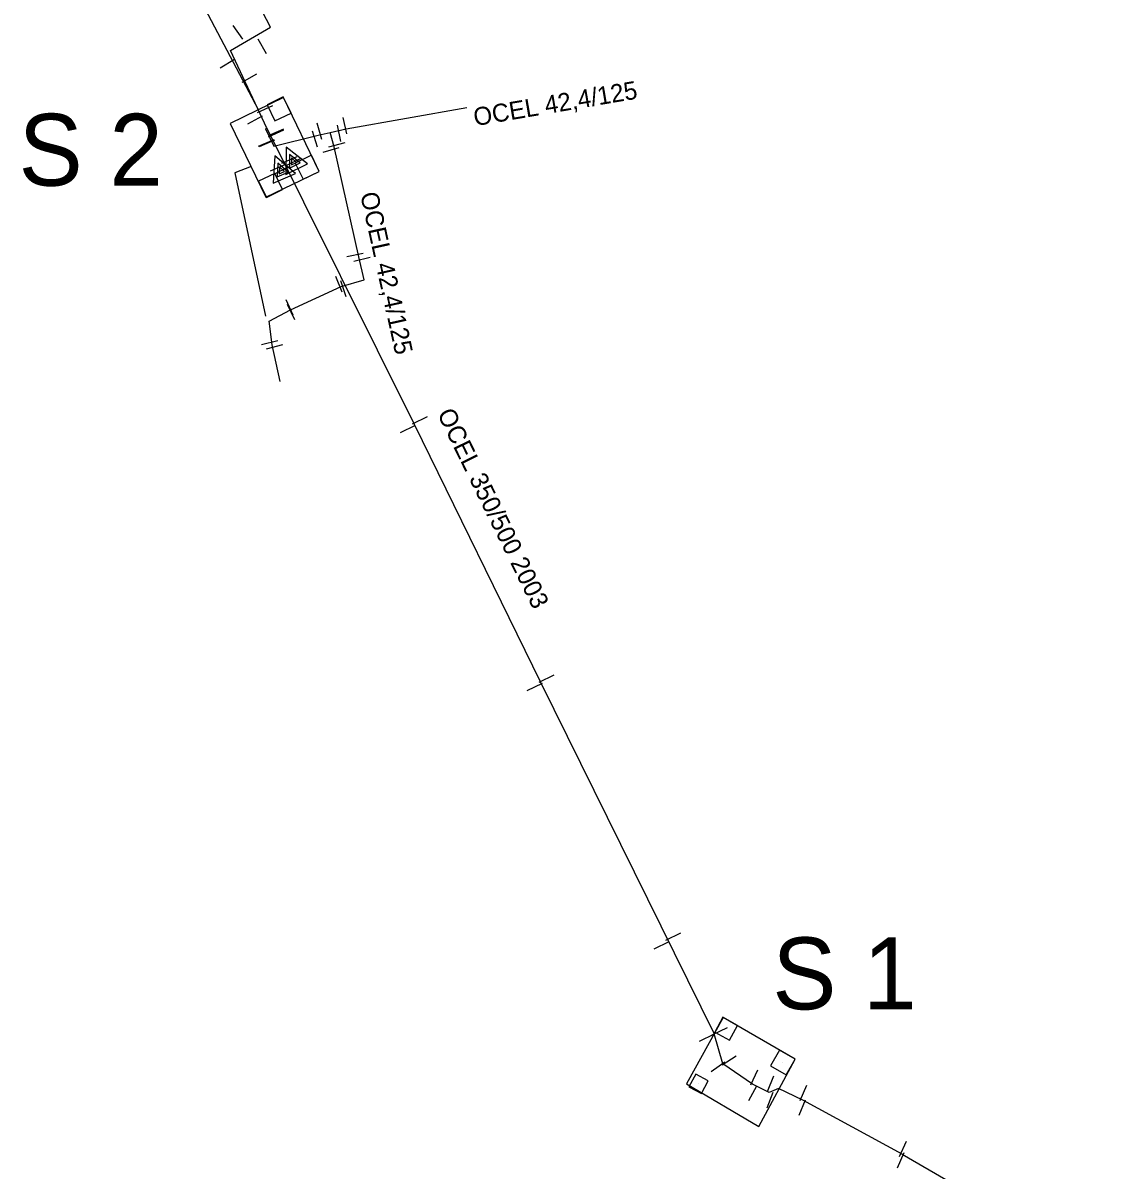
# Model space of a CAD drawing. Extents: x -642943 to -623314, y -1138561 to -1113539.
# Drawn here: x -642256.12 to -642210.58, y -1114828.93 to -1114781.07 of the extents above; entities that cross this region are included whole.
import ezdxf

# ---------------------------------------------------------------- set-up
doc = ezdxf.new("R2010")
doc.units = 0
for name, color, linetype in [('horkovod armatury', 7, 'Continuous'), ('horkovod dimenze', 7, 'Continuous'), ('horkovod předisol', 7, 'Continuous'), ('horkovod sváry', 7, 'Continuous'), ('horkovod trasa', 7, 'Continuous'), ('horkovod zrušený', 7, 'Continuous'), ('horkovod číslo šachty', 7, 'Continuous'), ('horkovod šachty', 7, 'Continuous')]:
    doc.layers.add(name, color=color, linetype=linetype)

# ---------------------------------------------------------------- blocks, each defined once
blk = doc.blocks.new('SPH')
at = {"layer": 'horkovod sváry'}
blk.add_line((0, -0.035), (0, 0.035), dxfattribs=at)
blk = doc.blocks.new('SPH_1')
at = {"layer": 'horkovod sváry'}
blk.add_line((0.0001, -0.035), (-0.0001, 0.035), dxfattribs=at)
blk = doc.blocks.new('SPH_2')
at = {"layer": 'horkovod sváry'}
blk.add_line((-0.0001, -0.0349), (0.0001, 0.0349), dxfattribs=at)
blk = doc.blocks.new('POINT_DISPLAY')
blk.add_line((0, 0), (0, 0))
blk = doc.blocks.new('PREDU_1')
at = {"layer": 'horkovod armatury'}
for p, q in [((-0.0007, 0.0677), (-0.0502, -0.0344)), ((0.0509, -0.0333), (-0.0007, 0.0677)), ((-0.0003, 0.0342), (-0.0249, -0.0171)), ((-0.0002, 0.0177), (-0.0119, -0.0084)), ((0.0251, -0.0166), (-0.0003, 0.0342)), ((0.0121, -0.0082), (-0.0002, 0.0177)), ((-0.0502, -0.0344), (0.0509, -0.0333)), ((-0.0249, -0.0171), (0.0251, -0.0166)), ((-0.0119, -0.0084), (0.0121, -0.0082))]:
    blk.add_line(p, q, dxfattribs=at)

msp = doc.modelspace()

# ---------------------------------------------------------------- linework, layer by layer
at = {"layer": 'horkovod předisol'}
for points in [[(-642245.948, -1114785.437), (-642246.214, -1114784.867), (-642247.454, -1114782.219), (-642245.787, -1114781.256), (-642247.074, -1114778.76), (-642248.776, -1114779.538), (-642252.188, -1114776.215)], [(-642243.291, -1114785.642), (-642242.626, -1114785.494), (-642237.585, -1114784.597)], [(-642245.948, -1114785.437), (-642245.998, -1114785.499), (-642245.641, -1114786.213), (-642243.799, -1114785.756), (-642243.291, -1114785.642)], [(-642245.948, -1114785.437), (-642239.784, -1114797.816), (-642234.509, -1114808.578), (-642227.271, -1114823.247)], [(-642245.387, -1114796.038), (-642245.71, -1114794.498), (-642245.834, -1114793.51), (-642244.954, -1114793.041), (-642242.835, -1114792.073), (-642241.881, -1114791.789), (-642242.097, -1114790.835), (-642243.121, -1114786.248), (-642243.291, -1114785.642)], [(-642219.415, -1114828.269), (-642223.564, -1114826.012), (-642224.576, -1114825.525), (-642224.968, -1114825.689), (-642225.663, -1114825.349), (-642226.903, -1114824.49), (-642227.271, -1114823.247)]]:
    msp.add_lwpolyline(points, dxfattribs=at)
at = {"layer": 'horkovod trasa'}
for points in [[(-642245.948, -1114785.437), (-642246.214, -1114784.867), (-642247.454, -1114782.219), (-642245.787, -1114781.256), (-642247.074, -1114778.76), (-642248.776, -1114779.538), (-642252.188, -1114776.215)], [(-642243.291, -1114785.642), (-642242.626, -1114785.494), (-642237.585, -1114784.597)], [(-642245.948, -1114785.437), (-642245.998, -1114785.499), (-642245.641, -1114786.213), (-642243.799, -1114785.756), (-642243.291, -1114785.642)], [(-642245.948, -1114785.437), (-642239.784, -1114797.816), (-642234.509, -1114808.578), (-642227.271, -1114823.247)], [(-642245.387, -1114796.038), (-642245.71, -1114794.498), (-642245.834, -1114793.51), (-642244.954, -1114793.041), (-642242.835, -1114792.073), (-642241.881, -1114791.789), (-642242.097, -1114790.835), (-642243.121, -1114786.248), (-642243.291, -1114785.642)], [(-642219.415, -1114828.269), (-642223.564, -1114826.012), (-642224.576, -1114825.525), (-642224.968, -1114825.689), (-642225.663, -1114825.349), (-642226.903, -1114824.49), (-642227.271, -1114823.247)], [(-642219.415, -1114828.269), (-642210.576, -1114833.393)]]:
    msp.add_lwpolyline(points, dxfattribs=at)
at = {"layer": 'horkovod zrušený'}
for p, q in [((-642246.288, -1114784.693), (-642249.014, -1114779.535)), ((-642246.598, -1114787.063), (-642247.268, -1114787.322)), ((-642247.268, -1114787.322), (-642245.992, -1114793.31))]:
    msp.add_line(p, q, dxfattribs=at)
at = {"layer": 'horkovod šachty'}
for p, q in [((-642245.254, -1114784.159), (-642245.929, -1114784.486)), ((-642244.927, -1114784.834), (-642245.254, -1114784.159)), ((-642245.929, -1114784.486), (-642245.602, -1114785.161)), ((-642245.602, -1114785.161), (-642244.927, -1114784.834)), ((-642244.077, -1114786.594), (-642244.752, -1114786.921)), ((-642243.75, -1114787.269), (-642244.077, -1114786.594)), ((-642244.752, -1114786.921), (-642244.425, -1114787.596)), ((-642245.61, -1114787.35), (-642246.285, -1114787.677)), ((-642245.283, -1114788.025), (-642245.61, -1114787.35)), ((-642244.425, -1114787.596), (-642243.75, -1114787.269)), ((-642246.285, -1114787.677), (-642245.958, -1114788.352)), ((-642245.958, -1114788.352), (-642245.283, -1114788.025)), ((-642226.909, -1114822.555), (-642227.245, -1114823.169)), ((-642226.295, -1114822.891), (-642226.909, -1114822.555)), ((-642226.631, -1114823.505), (-642226.295, -1114822.891)), ((-642227.245, -1114823.169), (-642226.631, -1114823.505)), ((-642224.539, -1114823.931), (-642224.914, -1114824.581)), ((-642223.89, -1114824.305), (-642224.539, -1114823.931)), ((-642224.264, -1114824.955), (-642223.89, -1114824.305)), ((-642224.914, -1114824.581), (-642224.264, -1114824.955)), ((-642228.039, -1114824.922), (-642228.328, -1114825.449)), ((-642227.512, -1114825.211), (-642228.039, -1114824.922)), ((-642227.801, -1114825.738), (-642227.512, -1114825.211)), ((-642228.328, -1114825.449), (-642227.801, -1114825.738))]:
    msp.add_line(p, q, dxfattribs=at)
for points in [[(-642245.973, -1114788.346), (-642243.75, -1114787.269), (-642245.241, -1114784.191), (-642247.464, -1114785.268), (-642245.973, -1114788.346)], [(-642225.404, -1114827.109), (-642223.89, -1114824.305), (-642226.895, -1114822.57), (-642228.428, -1114825.331), (-642225.404, -1114827.109)]]:
    msp.add_lwpolyline(points, dxfattribs=at)

# ---------------------------------------------------------------- block references
at = {"layer": 'horkovod armatury'}
for p, xscale, yscale, rotation in [((-642244.838, -1114786.867), 10.000022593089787, 10.000022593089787, 24.928558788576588), ((-642245.341, -1114787.243), 9.999996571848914, 9.999996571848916, 22.81544881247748)]:
    msp.add_blockref('PREDU_1', p, dxfattribs=dict(at, xscale=xscale, yscale=yscale, rotation=rotation))
at = {"layer": 'horkovod sváry'}
for name, p, xscale, yscale, rotation in [('SPH', (-642247.14, -1114781.47), 10.00000669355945, 10.000006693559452, 35.86628773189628), ('SPH_1', (-642246.13, -1114782.06), 9.999996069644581, 9.99999606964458, 29.65678752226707), ('SPH_1', (-642247.59, -1114782.77), 10.000005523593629, 10.00000552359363, -58.74706048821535), ('SPH_1', (-642246.66, -1114783.37), 10.000019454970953, 10.000019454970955, -59.84158513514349), ('SPH', (-642246.01, -1114784.66), 10.0000168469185, 10.000016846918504, -65.28363239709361), ('SPH', (-642246.43, -1114785.12), 9.999984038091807, 9.999984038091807, -61.27440701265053), ('SPH_1', (-642242.67, -1114785.36), 10.000000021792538, 10.000000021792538, 12.293214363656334), ('SPH_1', (-642245.55, -1114785.63), 9.999984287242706, 9.999984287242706, -66.58679541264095), ('SPH', (-642245.55, -1114785.68), 10.00001003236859, 10.000010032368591, -66.34590379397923), ('SPH_1', (-642243.93, -1114785.93), 10.000002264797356, 10.000002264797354, 17.37611636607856), ('SPH', (-642243.74, -1114785.6), 10.000009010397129, 10.000009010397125, 15.27365174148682), ('SPH_1', (-642242.92, -1114785.68), 9.99997943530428, 9.99997943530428, 11.980490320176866), ('SPH', (-642245.96, -1114786.08), 9.999999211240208, 9.999999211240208, -66.74083710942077), ('SPH_1', (-642245.93, -1114786.09), 9.999987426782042, 9.999987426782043, -66.33157371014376), ('SPH_1', (-642243.01, -1114786.15), 10.000015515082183, 10.000015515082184, -75.61865842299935), ('SPH_1', (-642243.25, -1114786.37), 9.99999972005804, 9.999999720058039, -73.37494270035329), ('SPH', (-642245.46, -1114787.11), 9.999989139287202, 9.999989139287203, -66.7686884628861), ('SPH', (-642245.337, -1114787.233), 10.00001383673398, 10.00001383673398, -63.83645896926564), ('SPH_1', (-642244.99, -1114786.79), 9.999983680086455, 9.999983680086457, -66.68502900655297), ('SPH', (-642244.843, -1114786.88), 10.00001383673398, 10.00001383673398, -63.83645896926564), ('SPH_1', (-642242.26, -1114790.75), 9.999998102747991, 9.999998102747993, -78.12615491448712), ('SPH_1', (-642241.96, -1114790.93), 10.00000482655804, 10.000004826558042, -76.99392444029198), ('SPH_1', (-642242.92, -1114791.98), 9.9999942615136, 9.9999942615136, 21.964906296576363), ('SPH', (-642242.74, -1114792.17), 10.000010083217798, 10.000010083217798, 18.92152208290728), ('SPH', (-642244.98, -1114792.95), 10.000020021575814, 10.000020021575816, 24.87418252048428), ('SPH_1', (-642244.92, -1114793.14), 9.999985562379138, 9.999985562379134, 26.12082257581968), ('SPH_1', (-642245.82, -1114794.41), 9.999993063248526, 9.999993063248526, -76.3495586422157), ('SPH_1', (-642245.61, -1114794.58), 9.999992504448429, 9.999992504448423, -75.43979480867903), ('SPH', (-642239.549, -1114797.65), 10.00001383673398, 10.00001383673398, -63.83645896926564), ('SPH', (-642240.042, -1114798.003), 10.00001383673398, 10.00001383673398, -63.83645896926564), ('SPH', (-642234.751, -1114808.774), 10.00001383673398, 10.00001383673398, -63.83645896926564), ('SPH', (-642234.258, -1114808.42), 10.00001383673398, 10.00001383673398, -63.83645896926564), ('SPH', (-642228.966, -1114819.19), 10.00001383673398, 10.00001383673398, -63.83645896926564), ('SPH', (-642229.459, -1114819.544), 10.00001383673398, 10.00001383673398, -63.83645896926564), ('SPH', (-642227.03, -1114823.13), 10.00001383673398, 10.00001383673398, -63.83645896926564), ('SPH', (-642227.568, -1114823.394), 10.00001383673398, 10.00001383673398, -63.83645896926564), ('SPH_2', (-642227.11, -1114824.62), 9.99999281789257, 9.999992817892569, -54.76525142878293), ('SPH_2', (-642226.64, -1114824.35), 9.999980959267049, 9.999980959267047, -56.621541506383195), ('SPH_2', (-642225.59, -1114825.06), 9.999998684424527, 9.999998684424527, -25.614634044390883), ('SPH_2', (-642224.91, -1114825.32), 9.999992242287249, 9.99999224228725, -21.853332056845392), ('SPH', (-642225.65, -1114825.72), 10.000021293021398, 10.000021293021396, -28.429253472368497), ('SPH_1', (-642224.93, -1114826.01), 10.000017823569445, 10.000017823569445, -20.640358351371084), ('SPH_2', (-642223.54, -1114825.71), 9.999997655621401, 9.999997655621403, -22.385548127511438), ('SPH_2', (-642223.59, -1114826.32), 9.999979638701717, 9.999979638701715, -22.289825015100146), ('SPH_2', (-642219.39, -1114828.04), 10.000009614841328, 10.00000961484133, -24.561403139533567), ('SPH_2', (-642219.48, -1114828.51), 9.999996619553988, 9.999996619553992, -23.5813309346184)]:
    msp.add_blockref(name, p, dxfattribs=dict(at, xscale=xscale, yscale=yscale, rotation=rotation))
at = {"layer": 'horkovod šachty'}
for p in [(-642244.244, -1114787.097), (-642226.77, -1114823.03), (-642224.4, -1114824.45), (-642227.92, -1114825.33)]:
    msp.add_blockref('POINT_DISPLAY', p, dxfattribs=at)

# ---------------------------------------------------------------- texts
at = {"layer": 'horkovod dimenze'}
for s, rotation, p in [('OCEL 42,4/125', 9.6132, (-642237.246, -1114785.381)), ('OCEL 42,4/125', 282.3891, (-642242.045, -1114788.211)), ('OCEL 350/500 2003', 296.1636, (-642238.839, -1114797.376))]:
    msp.add_text(s, height=0.75, rotation=rotation, dxfattribs=at).set_placement(p)
at = {"layer": 'horkovod číslo šachty'}
for s, p in [('S 2', (-642256.3, -1114787.865)), ('S 1', (-642224.84, -1114822.224))]:
    msp.add_text(s, height=3, dxfattribs=at).set_placement(p)

doc.saveas('drawing.dxf')
